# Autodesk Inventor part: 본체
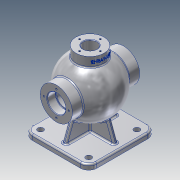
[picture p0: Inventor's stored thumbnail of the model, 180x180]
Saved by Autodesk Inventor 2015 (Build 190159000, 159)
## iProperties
Created: 2025-08
Part Number: 본체
Material: 알루미늄 6061
Document SubType Name: Modeling
Designer: user
Density: 2.7 g/cm^3
Appearance: 알루미늄 - 평지
Author: user
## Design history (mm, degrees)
sketch "스케치2"
  geometry: L1 (-62.5, 65)-(62.5, 65); L2 (62.5, 65)-(62.5, -65); L3 (62.5, -65)-(-62.5, -65); L4 (-62.5, -65)-(-62.5, 65); L5 (-62.5, 65)-(62.5, -65); L6 (62.5, 65)-(-62.5, -65); 1 further point
  constraints: 12 end point, 2 midpoint, 2 parallel, 1 horizontal, 1 perpendicular
  dimensions: "d4" = 125 distance of L2.end L3.end; "d5" = 130 distance of L1.end L2.end
extrude "돌출2" new body sketch "스케치2" distance "d6" = 10; taper "d7" = 0 deg
sketch "스케치4"
  geometry: L1 (62.5, 10)-(62.5, 0) reference; L2 (62.5, 0)-(-62.5, 0) reference; L3 (-62.5, 0)-(-62.5, 10) reference; L4 (-62.5, 10)-(62.5, 10) reference; L5 (0, 139)-(0, 31); L6 (-62.5, 0)-(62.5, 0) reference; A1 r 54 centre (0, 85) between (0, 139) and (0, 31); 3 further points
  constraints: 2 end point, 2 midpoint, 2 point on circle, 1 centre point, 1 coincident, 1 vertical, 1 vertical alignment
  dimensions: "d12" = 108 diameter of A1; "d13" = 85 distance from line of A1.centre L2
revolve "회전1" sketch "스케치4" stored, may be unused: angle "d14" = 90 deg
node "작업 평면1"
sketch "스케치5"
  geometry: C1 r 27 at (0, 0); 1 further point
  constraints: 1 centre point, 1 coincident
  dimensions: "d16" = 54 diameter of C1
extrude "돌출3" join sketch "스케치5" stored distance "d17" = 10; taper "d18" = 0 deg
sketch "스케치6"
  geometry: L1 (-50.5, 4)-(50.5, 4); L2 (50.5, 4)-(50.5, -4); L3 (50.5, -4)-(-50.5, -4); L4 (-50.5, -4)-(-50.5, 4); L5 (-50.5, 4)-(50.5, -4); L6 (50.5, 4)-(-50.5, -4); L7 (-4, -50.5)-(4, -50.5); L8 (4, -50.5)-(4, 50.5); L9 (4, 50.5)-(-4, 50.5); L10 (-4, 50.5)-(-4, -50.5); L11 (-4, -50.5)-(4, 50.5); L12 (4, -50.5)-(-4, 50.5); 1 further point
  constraints: 24 end point, 4 midpoint, 4 parallel, 2 horizontal, 2 perpendicular
  dimensions: "d19" = 101 distance of L2.end L3.end; "d20" = 8 distance of L1.end L2.end; "d21" = 8 distance of L9.end L8.end; "d22" = 101 distance of L8.end L7.end
extrude "돌출4" join sketch "스케치6" distance "d23" = 85; taper "d24" = 0 deg
feature "면 기울기1" dims angle "d25" = 20 deg
node "작업 평면2"
sketch "스케치7"
  geometry: L1 (-62.5, 0)-(62.5, 0) reference; C1 r 31 at (0, 85); 3 further points
  constraints: 2 midpoint, 2 vertical alignment, 1 centre point
  dimensions: "d27" = 62 diameter of C1; "d28" = 85 distance of point (0, 0) C1.centre
extrude "돌출5" join sketch "스케치7" distance "d29" = 60; taper "d30" = 0 deg
hole "구멍1" diameter "d33" = 30; stored, may be unused: countersink angle "d37" = 90 deg, drill point angle "d39" = 0 deg; dims "d34" = 6, "d35" = 35, "d36" = 16, "d38" = 20, "d69" = 10, "d70" = 10
fillet "모깎기1" dims "d42" = 16
hole "구멍2" diameter "d45" = 11; stored, may be unused: countersink angle "d49" = 90 deg, drill point angle "d51" = 0 deg; dims "d43" = 16, "d44" = 16, "d46" = 6, "d47" = 35, "d48" = 16, "d50" = 20
hole "구멍3" diameter "d60" = 26; stored, may be unused: countersink angle "d64" = 90 deg, drill point angle "d66" = 0 deg; dims "d58" = 10, "d59" = 10, "d61" = 6, "d62" = 35, "d63" = 16, "d65" = 100
sketch "스케치11"
  geometry: L1 (-27, 131.765)-(-27, 150) reference; L2 (-27, 150)-(-13, 150) reference; L3 (-13, 150)-(-13, 92.483) reference; L4 (-13, 50)-(13, 50) reference; L5 (13, 50)-(13, 77.517) reference; L6 (13, 150)-(27, 150) reference; L7 (27, 150)-(27, 131.765) reference; L8 (37.385, 46.034)-(50.5, 10) reference; L9 (50.5, 10)-(62.5, 10) reference; L10 (62.5, 10)-(62.5, 0) reference; L11 (62.5, 0)-(-62.5, 0) reference; L12 (-62.5, 0)-(-62.5, 10) reference; L13 (-62.5, 10)-(-50.5, 10) reference; L14 (-50.5, 10)-(-37.385, 46.034) reference; L15 (0, 129)-(0, 41); L16 (4, 10)-(4, 46.186) reference; L17 (-13, 77.517)-(-13, 50) reference; L18 (13, 92.483)-(13, 150) reference; C1 r 17.5 at (0, 85) reference; A1 r 54 centre (0, 85) between (37.385, 46.034) and (27, 131.765) reference; A2 r 54 centre (0, 85) between (-27, 131.765) and (-37.385, 46.034) reference; A3 r 44 centre (0, 85) between (0, 129) and (4, 41.182); A4 r 15 centre (0, 85) between (-13, 92.483) and (-13, 77.517) reference; A5 r 15 centre (0, 85) between (13, 77.517) and (13, 92.483) reference; 2 further points
  constraints: 3 point on circle, 2 coincident, 2 end point, 1 centre point, 1 midpoint, 1 parallel, 1 point on line
  dimensions: "d67" = 88 diameter of A3
revolve "회전2" sketch "스케치11" stored, may be unused: angle "d68" = 90 deg
sketch "스케치14"
  geometry: C1 r 3.442 at (0, 20); 1 further point
  constraints: 1 centre point, 1 vertical alignment
  dimensions: "d71" = 20 distance of point (0, 0) C1.centre
hole "구멍4" sketch "스케치14" at (0, 20) diameter "d72" = 3.242; stored, may be unused: countersink angle "d76" = 90 deg, drill point angle "d78" = 118 deg; dims "d73" = 12, "d74" = 35, "d75" = 16, "d77" = 15
sketch "스케치15"
  geometry: L1 (-46.5, -75)-(46.5, -75) reference; L2 (46.5, -85)-(46.5, -75) reference; L3 (46.5, -85)-(-46.5, -85) reference; L4 (-46.5, -85)-(-46.5, -75) reference; C1 r 3.321 at (0, 24); C2 r 17.5 at (0, 0) reference; C3 r 31 at (0, 0) reference; 1 further point
  constraints: 1 centre point, 1 vertical alignment
  dimensions: "d82" = 24 distance of C2.centre C1.centre
hole "구멍5" sketch "스케치15" at (0, 24) diameter "d83" = 3.242; stored, may be unused: countersink angle "d87" = 90 deg, drill point angle "d89" = 118 deg; dims "d84" = 12, "d85" = 35, "d86" = 16, "d88" = 15
chamfer "모따기1" distance "d94" = 1; stored, may be unused: second distance "d95" = 2, angle "d96" = 45 deg
fillet "모깎기3" dims "d97" = 0.6
fillet "모깎기4" dims "d98" = 3
fillet "모깎기5" dims "d99" = 3
fillet "모깎기6" dims "d100" = 3
fillet "모깎기7" dims "d101" = 3
fillet "모깎기8" dims "d102" = 3
sketch "스케치16"
  geometry: L1 (14, 150)-(-14, 150) reference; 2 further points
  constraints: 1 vertical alignment, 1 other
  dimensions: "d103" = 9 distance from line of point (0, 141) L1
feature "엠보싱1" sketch "스케치16" dims "d17" = 10, "d104" = 1, "d105" = 0
fillet "모깎기9" dims "d106" = 3
node "솔리드2"
mirror "대칭1"
mirror "대칭2"
pattern_linear "직사각형 패턴1" dims "d54" = 93, "d57" = 93
pattern_circular "원형 패턴1" dims angle "d80" = 360 deg
pattern_circular "원형 패턴2" dims angle "d91" = 360 deg
mirror "대칭3"
node "작업 평면3"
node "절단 모서리 투영1"
node "절단 모서리 투영2"
node "절단 모서리 투영3"
other parameters: "d26" = -65
